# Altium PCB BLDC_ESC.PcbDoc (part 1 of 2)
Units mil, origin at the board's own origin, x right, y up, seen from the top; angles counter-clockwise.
Board outline 1574.8 x 2362.2 mil, 2 copper layers (Top Layer, Bottom Layer), stack 65.792 mil thick; 131 components, 100 nets, 479 pads, 292 vias.
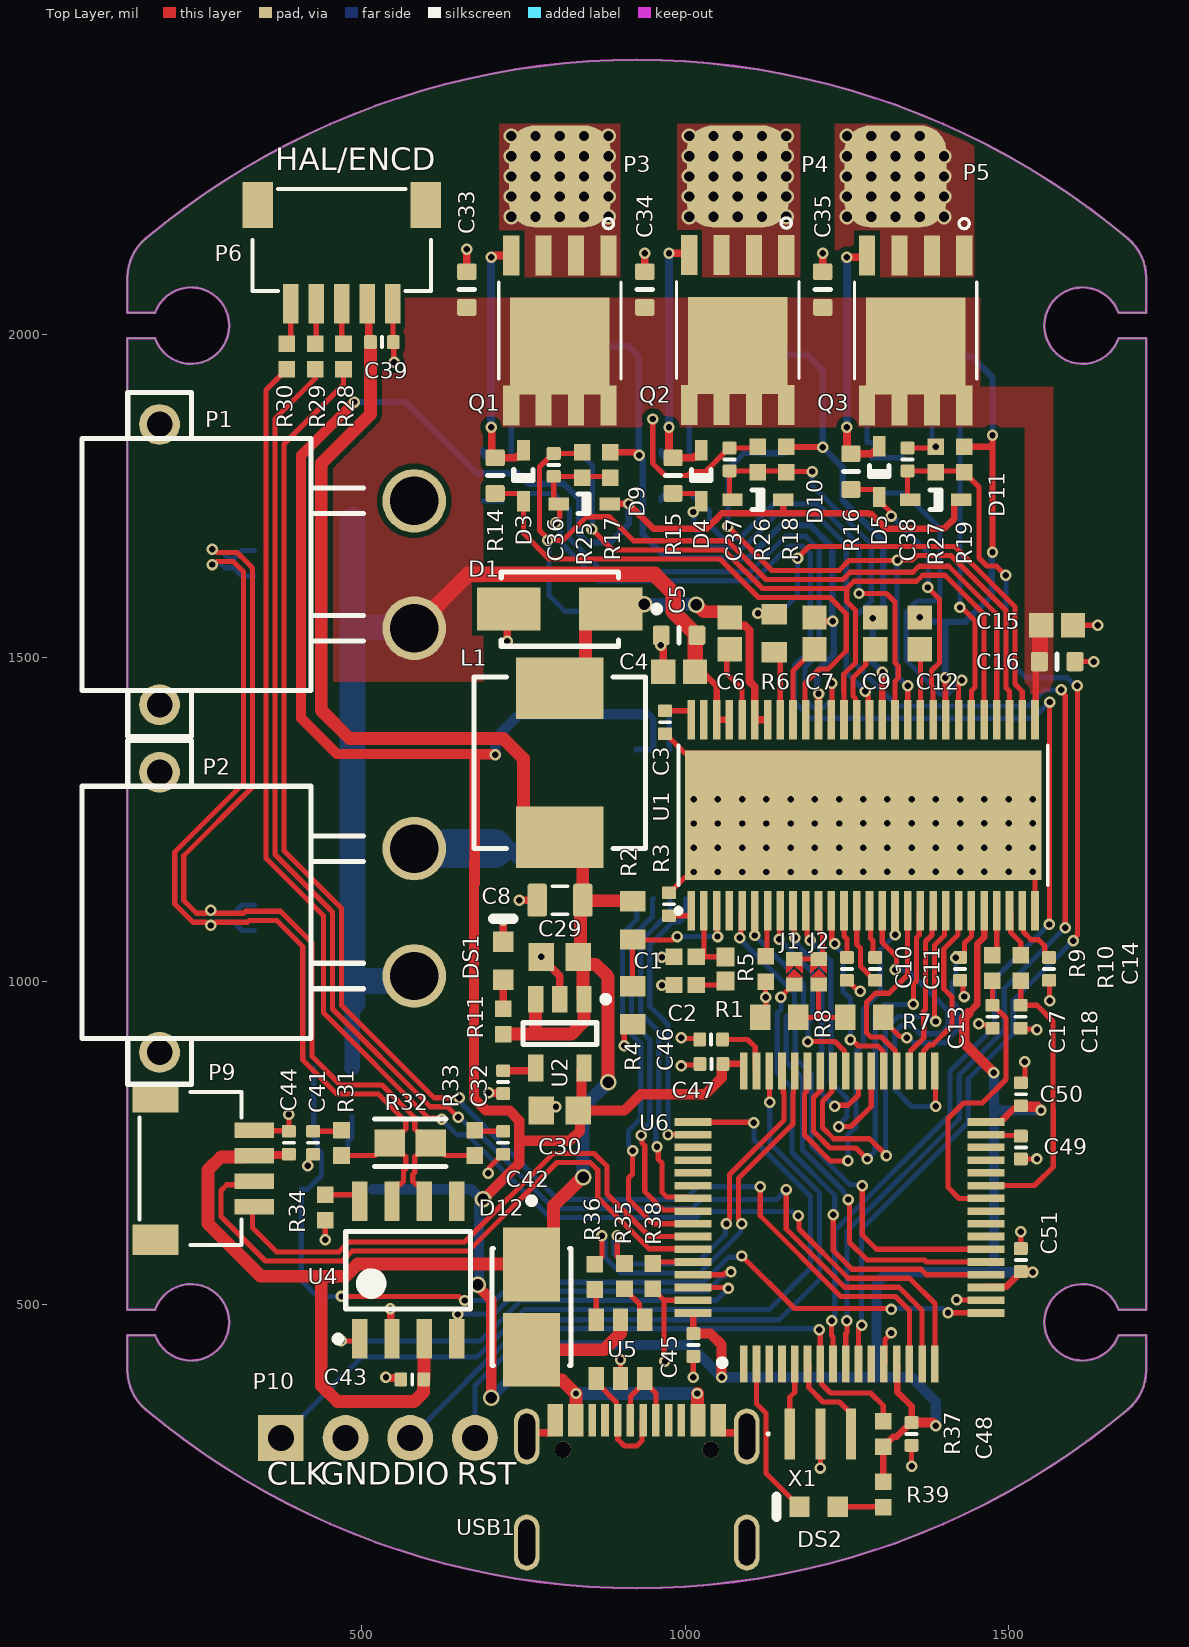
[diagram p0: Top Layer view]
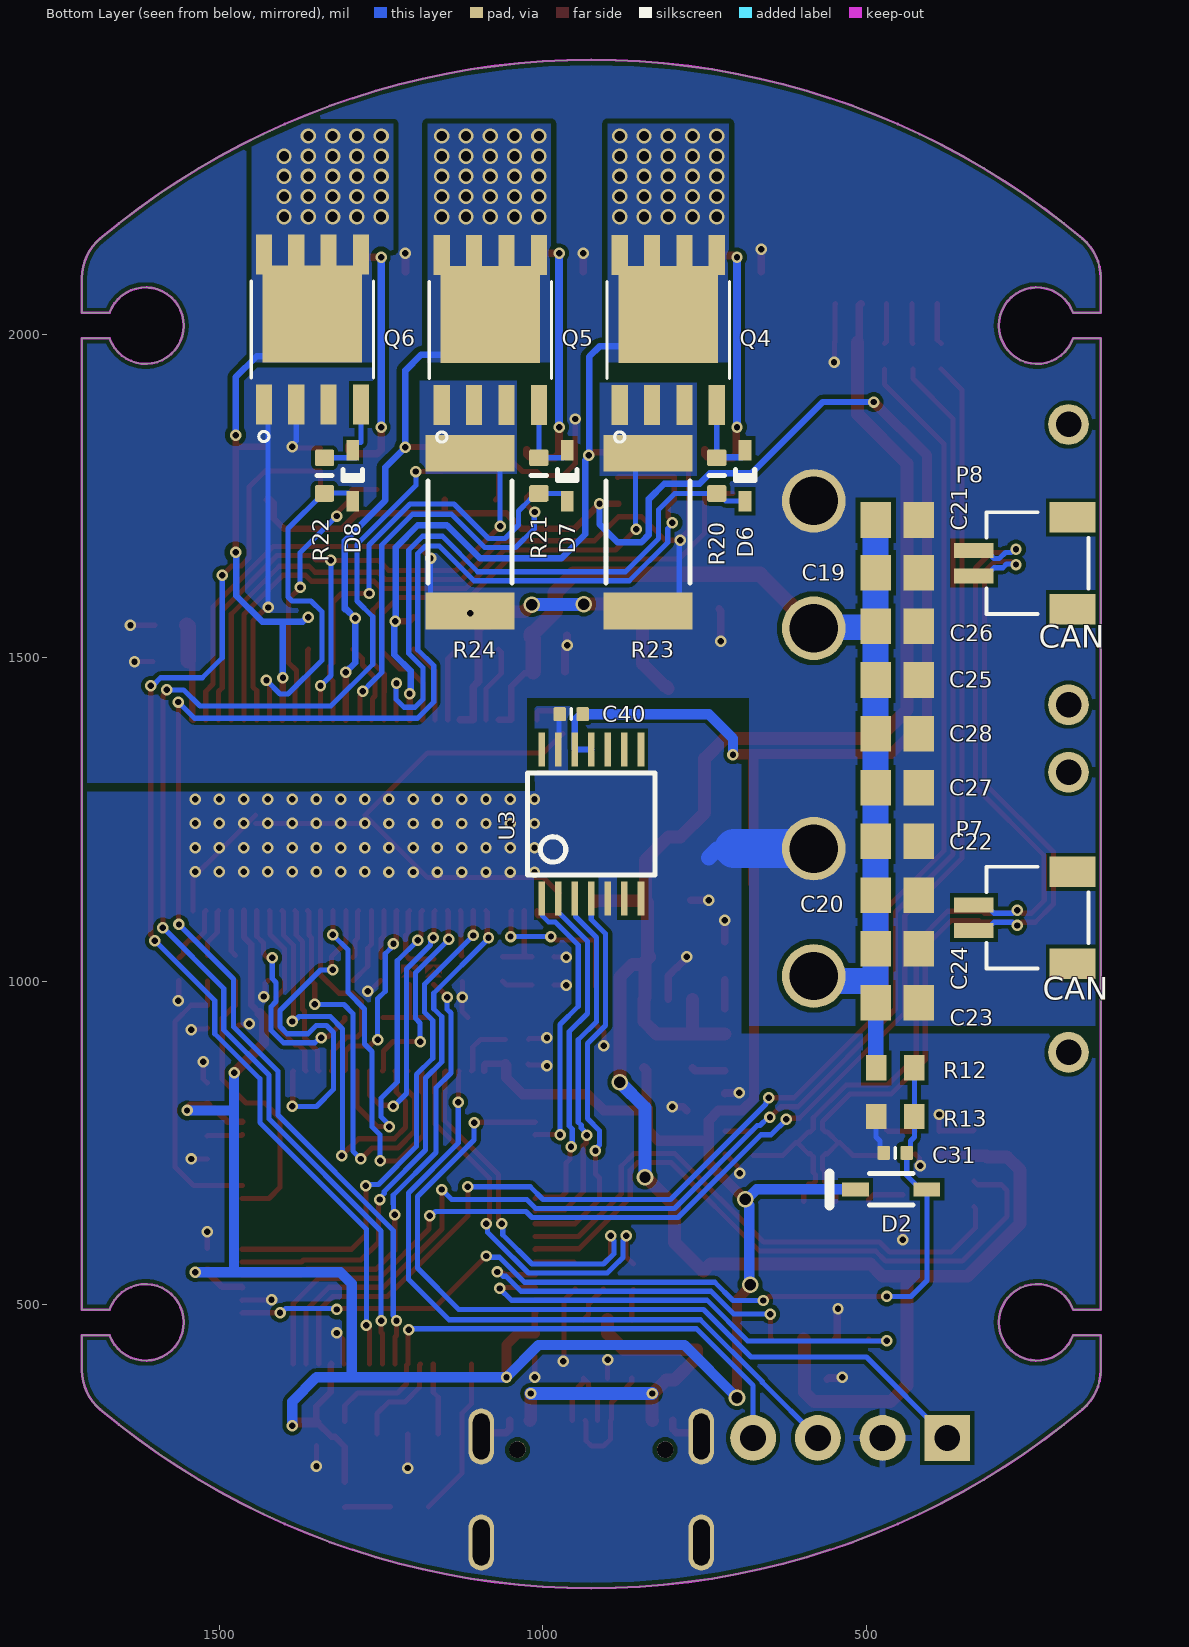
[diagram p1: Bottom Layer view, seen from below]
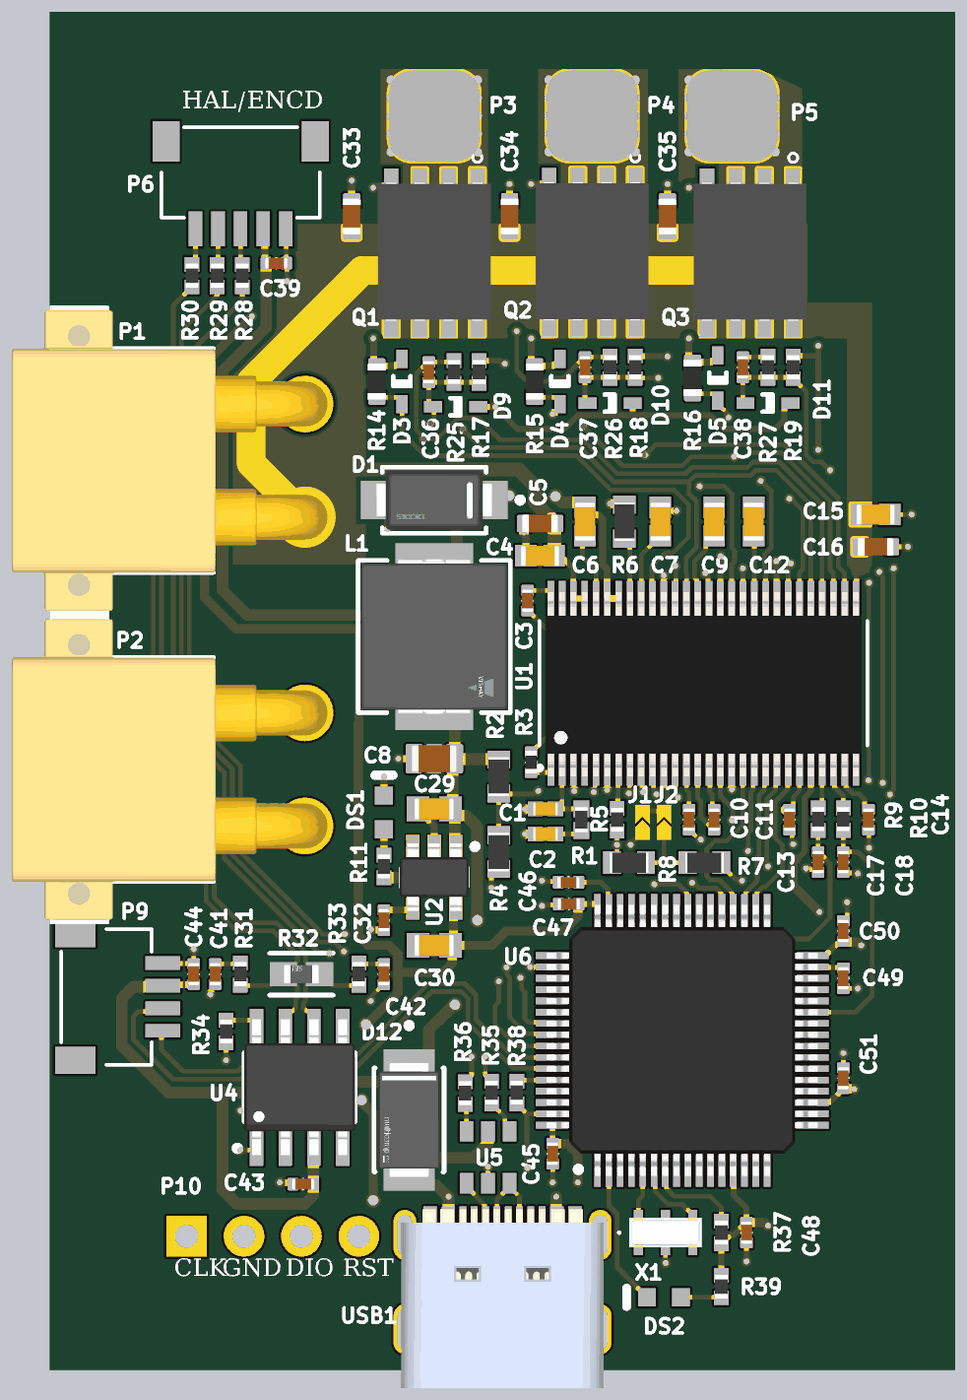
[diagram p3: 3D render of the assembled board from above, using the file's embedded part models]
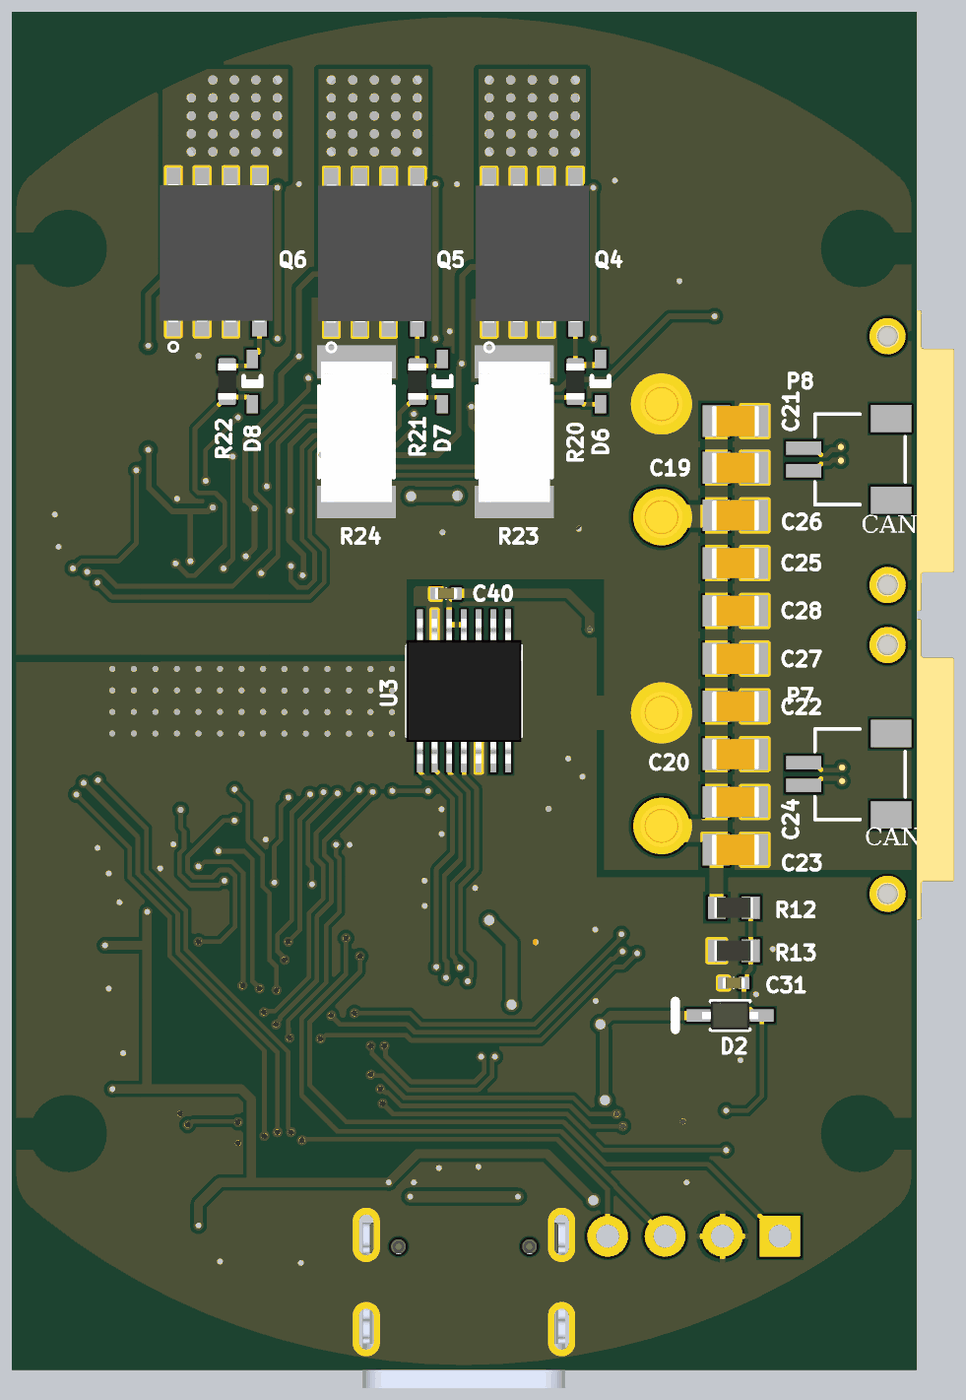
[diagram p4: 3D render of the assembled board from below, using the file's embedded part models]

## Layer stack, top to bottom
Top Solder: solder mask 0.4, Solder Resist, Dk 3.5
Top Layer: signal copper 1.4
Dielectric 1: dielectric 62.9921, FR-4, Dk 4.8
Bottom Layer: signal copper 1.4
Bottom Solder: solder mask 0.4, Solder Resist, Dk 3.5

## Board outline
165.92,338.03 cw(c216.54,398.35) 137.8,398.35 137.8,452.76 180.54,452.76 ccw(c236.22,472.44) 180.54,492.13 137.8,492.13 137.8,1993.35 180.54,1993.35 ccw(c236.22,2013.04) 180.54,2032.72 137.8,2032.72 137.8,2087.13 cw(c216.54,2087.13) 165.92,2147.45 cw(c925.2,1242.74) 1684.48,2147.45 cw(c1633.86,2087.13) 1712.6,2087.13 1712.6,2032.72 1669.85,2032.72 ccw(c1614.17,2013.04) 1669.85,1993.35 1712.6,1993.35 1712.6,492.13 1669.85,492.13 ccw(c1614.17,472.44) 1669.85,452.76 1712.6,452.76 1712.6,398.35 cw(c1633.86,398.35) 1684.48,338.03 cw(c925.2,1242.74)

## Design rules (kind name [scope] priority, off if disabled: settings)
Clearance Clearance_POWER [InNetClass('POWER_OUT')     or InNet('PVDD')] p1: gap=8 ignorepadtopadclearanceinfootprint=TRUE
Clearance [All] p2: gap=6 ignorepadtopadclearanceinfootprint=TRUE except(0: Arc-Region Track-Region SMDPad-Region THPad-Region Via-Region Fill-Region Poly-Region Region-Region)
ComponentClearance [All] p1: gap=0 collisioncheckmode=3 verticalgap=0 showdistances=FALSE
DiffPairsRouting [All] p1: maxlimit=10 minlimit=6 mostfreqgap=6 toplayer_minwidth=8 toplayer_maxwidth=8 toplayer_prefwidth=8 bottomlayer_minwidth=8 bottomlayer_maxwidth=8 bottomlayer_prefwidth=8 maxuncoupledlength=500
MinimumSolderMaskSliver [All] p1: minsoldermaskwidth=0
PolygonConnect PolygonConnect_15 [All vs IsNamedPolygon('PVDD')] p1: connectstyle=Direct reliefconductorwidth=10 reliefentries=4 polygonreliefangle="90 Angle" airgapwidth=10
PolygonConnect PolygonConnect_14 [All vs IsNamedPolygon('GNDA')] p2: connectstyle=Direct reliefconductorwidth=10 reliefentries=4 polygonreliefangle="90 Angle" airgapwidth=10
PolygonConnect PolygonConnect_13 [All vs IsNamedPolygon('GNDA')] p3: thpad.connectstyle=Relief thpad.reliefconductorwidth=10 thpad.reliefentries=4 thpad.polygonreliefangle="90 Angle" thpad.airgapwidth=10 smdpad.connectstyle=Direct smdpad.reliefconductorwidth=10 smdpad.reliefentries=4 smdpad.polygonreliefangle="90 Angle" smdpad.airgapwidth=10 via.connectstyle=Direct via.reliefconductorwidth=10 via.reliefentries=4 via.polygonreliefangle="90 Angle" via.airgapwidth=10
PolygonConnect PolygonConnect_12 [All vs IsNamedPolygon('SL_B')] p4: thpad.connectstyle=Relief thpad.reliefconductorwidth=10 thpad.reliefentries=4 thpad.polygonreliefangle="90 Angle" thpad.airgapwidth=10 smdpad.connectstyle=Direct smdpad.reliefconductorwidth=10 smdpad.reliefentries=4 smdpad.polygonreliefangle="90 Angle" smdpad.airgapwidth=10 via.connectstyle=Direct via.reliefconductorwidth=10 via.reliefentries=4 via.polygonreliefangle="90 Angle" via.airgapwidth=10
PolygonConnect PolygonConnect_11 [All vs IsNamedPolygon('SL_A')] p5: thpad.connectstyle=Relief thpad.reliefconductorwidth=10 thpad.reliefentries=4 thpad.polygonreliefangle="90 Angle" thpad.airgapwidth=10 smdpad.connectstyle=Direct smdpad.reliefconductorwidth=10 smdpad.reliefentries=4 smdpad.polygonreliefangle="90 Angle" smdpad.airgapwidth=10 via.connectstyle=Direct via.reliefconductorwidth=10 via.reliefentries=4 via.polygonreliefangle="90 Angle" via.airgapwidth=10
PolygonConnect PolygonConnect_10 [All vs IsNamedPolygon('SH_C')] p6: thpad.connectstyle=Relief thpad.reliefconductorwidth=10 thpad.reliefentries=4 thpad.polygonreliefangle="90 Angle" thpad.airgapwidth=10 smdpad.connectstyle=Direct smdpad.reliefconductorwidth=10 smdpad.reliefentries=4 smdpad.polygonreliefangle="90 Angle" smdpad.airgapwidth=10 via.connectstyle=Direct via.reliefconductorwidth=10 via.reliefentries=4 via.polygonreliefangle="90 Angle" via.airgapwidth=10
PolygonConnect PolygonConnect_9 [All vs IsNamedPolygon('SH_B')] p7: thpad.connectstyle=Relief thpad.reliefconductorwidth=10 thpad.reliefentries=4 thpad.polygonreliefangle="90 Angle" thpad.airgapwidth=10 smdpad.connectstyle=Direct smdpad.reliefconductorwidth=10 smdpad.reliefentries=4 smdpad.polygonreliefangle="90 Angle" smdpad.airgapwidth=10 via.connectstyle=Direct via.reliefconductorwidth=10 via.reliefentries=4 via.polygonreliefangle="90 Angle" via.airgapwidth=10
PolygonConnect PolygonConnect_8 [All vs IsNamedPolygon('SH_A')] p8: thpad.connectstyle=Relief thpad.reliefconductorwidth=10 thpad.reliefentries=4 thpad.polygonreliefangle="90 Angle" thpad.airgapwidth=10 smdpad.connectstyle=Direct smdpad.reliefconductorwidth=10 smdpad.reliefentries=4 smdpad.polygonreliefangle="90 Angle" smdpad.airgapwidth=10 via.connectstyle=Direct via.reliefconductorwidth=10 via.reliefentries=4 via.polygonreliefangle="90 Angle" via.airgapwidth=10
PolygonConnect PolygonConnect_7 [All vs IsNamedPolygon('SH_C')] p9: thpad.connectstyle=Relief thpad.reliefconductorwidth=10 thpad.reliefentries=4 thpad.polygonreliefangle="90 Angle" thpad.airgapwidth=10 smdpad.connectstyle=Direct smdpad.reliefconductorwidth=10 smdpad.reliefentries=4 smdpad.polygonreliefangle="90 Angle" smdpad.airgapwidth=10 via.connectstyle=Direct via.reliefconductorwidth=10 via.reliefentries=4 via.polygonreliefangle="90 Angle" via.airgapwidth=10
PolygonConnect PolygonConnect_6 [All vs IsNamedPolygon('SH_B')] p10: thpad.connectstyle=Relief thpad.reliefconductorwidth=10 thpad.reliefentries=4 thpad.polygonreliefangle="90 Angle" thpad.airgapwidth=10 smdpad.connectstyle=Direct smdpad.reliefconductorwidth=10 smdpad.reliefentries=4 smdpad.polygonreliefangle="90 Angle" smdpad.airgapwidth=10 via.connectstyle=Direct via.reliefconductorwidth=10 via.reliefentries=4 via.polygonreliefangle="90 Angle" via.airgapwidth=10
PolygonConnect PolygonConnect_5 [All vs IsNamedPolygon('SH_A')] p11: thpad.connectstyle=Relief thpad.reliefconductorwidth=10 thpad.reliefentries=4 thpad.polygonreliefangle="90 Angle" thpad.airgapwidth=10 smdpad.connectstyle=Direct smdpad.reliefconductorwidth=10 smdpad.reliefentries=4 smdpad.polygonreliefangle="90 Angle" smdpad.airgapwidth=10 via.connectstyle=Direct via.reliefconductorwidth=10 via.reliefentries=4 via.polygonreliefangle="90 Angle" via.airgapwidth=10
PolygonConnect PolygonConnect_4 [All vs IsNamedPolygon('SL_B')] p12: thpad.connectstyle=Relief thpad.reliefconductorwidth=10 thpad.reliefentries=4 thpad.polygonreliefangle="90 Angle" thpad.airgapwidth=10 smdpad.connectstyle=Direct smdpad.reliefconductorwidth=10 smdpad.reliefentries=4 smdpad.polygonreliefangle="90 Angle" smdpad.airgapwidth=10 via.connectstyle=Relief via.reliefconductorwidth=10 via.reliefentries=4 via.polygonreliefangle="90 Angle" via.airgapwidth=10
PolygonConnect PolygonConnect_3 [All vs IsNamedPolygon('SL_A')] p13: thpad.connectstyle=Relief thpad.reliefconductorwidth=10 thpad.reliefentries=4 thpad.polygonreliefangle="90 Angle" thpad.airgapwidth=10 smdpad.connectstyle=Direct smdpad.reliefconductorwidth=10 smdpad.reliefentries=4 smdpad.polygonreliefangle="90 Angle" smdpad.airgapwidth=10 via.connectstyle=Relief via.reliefconductorwidth=10 via.reliefentries=4 via.polygonreliefangle="90 Angle" via.airgapwidth=10
PolygonConnect PolygonConnect_2 [All vs IsNamedPolygon('GND')] p14: thpad.connectstyle=Relief thpad.reliefconductorwidth=10 thpad.reliefentries=4 thpad.polygonreliefangle="90 Angle" thpad.airgapwidth=10 smdpad.connectstyle=Direct smdpad.reliefconductorwidth=10 smdpad.reliefentries=4 smdpad.polygonreliefangle="90 Angle" smdpad.airgapwidth=10 via.connectstyle=Direct via.reliefconductorwidth=10 via.reliefentries=4 via.polygonreliefangle="90 Angle" via.airgapwidth=10
PolygonConnect PolygonConnect_1 [All vs IsNamedPolygon('PVDD')] p15: thpad.connectstyle=Relief thpad.reliefconductorwidth=10 thpad.reliefentries=4 thpad.polygonreliefangle="90 Angle" thpad.airgapwidth=10 smdpad.connectstyle=Direct smdpad.reliefconductorwidth=10 smdpad.reliefentries=4 smdpad.polygonreliefangle="90 Angle" smdpad.airgapwidth=10 via.connectstyle=Direct via.reliefconductorwidth=10 via.reliefentries=4 via.polygonreliefangle="90 Angle" via.airgapwidth=10
PolygonConnect [All] p16: connectstyle=Relief reliefconductorwidth=10 reliefentries=4 polygonreliefangle="90 Angle" airgapwidth=10
RoutingVias RoutingVias_signal [All] p1: holewidth=9.84 width=17.72 viastyle="Through Hole" minholewidth=9.84 minwidth=17.72 maxholewidth=17.72 maxwidth=25.59
SilkToSilkClearance [All] p1: silktosilkclearance=0
SilkToSolderMaskClearance [IsPad] p1: minsilkscreentomaskgap=0 clearancetoexposedcopper=TRUE
SolderMaskExpansion [All] p1: expansion=4 istentingtop=FALSE
UnRoutedNet [All] p1: checkbadconnections=TRUE
Width HIGH_POWER [InNet('PVDD')or InNetClass('POWER_OUT')  or InNet('GND')] p1: maxlimit=60 minlimit=8 preferedwidth=24
Width MID_POWER [InNetClass('MID_POWER')  or InNet('VBUS')] p2: maxlimit=20 minlimit=12 preferedwidth=20
Width LOW_POWER [InNet('+3V3')] p3: maxlimit=16 minlimit=10 preferedwidth=10
Width signal [All] p4: maxlimit=12 minlimit=8 preferedwidth=8
24 further rules are at their usual default settings.

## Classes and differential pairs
net class POWER_OUT: SH_A SH_B SH_C
net class MID_POWER: +5V NetC6_2
component class "rotor angle sensor": C39 C40 P6 R28 R29 R30 U3
component class "power MOSFET": C19 C20 C21 C22 C23 C24 C25 C26 C27 C28 C29 C30 C31 C32 C33 C34 C35 C36 C37 C38 D2 D3 D4 D5 D6 D7 D8 D9 D10 D11 DS1 P1 P2 P3 P4 P5 Q1 Q2 Q3 Q4 Q5 Q6 R11 R12 R13 R14 R15 R16 R17 R18 R19 R20 R21 R22 R23 R24 R25 R26 R27 U2
component class "main controller": C44 C45 C46 C47 C48 C49 C50 C51 D12 DS2 P9 P10 R35 R36 R37 R38 R39 U5 U6 USB1 X1
component class "gate driver": C1 C2 C3 C4 C5 C6 C7 C8 C9 C10 C11 C12 C13 C14 C15 C16 C17 C18 D1 J1 J2 R1 R2 R3 R4 R5 R6 R7 R8 R9 R10 U1
component class CAN: C41 C42 C43 P7 P8 R31 R32 R33 R34 U4
differential pair CAN1: +CAN1_P -CAN1_N
differential pair USB: +USB_P -USB_N

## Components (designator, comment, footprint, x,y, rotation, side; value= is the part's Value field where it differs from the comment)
C1 "Capacitor 6.8 nF +/- 10% 16 V 0402" CAPC1005X56X25NL10T15 1000,1037.5 r0 top value=120pF
C2 "Capacitor 6.8 nF +/- 10% 16 V 0402" CAPC1005X56X25NL10T15 1000,993.75 r0 top value=6.8nF
C3 "Capacitor 22nF +/-20% 10V 0402" CAPC0402(1005)60_L 968.75,1400 r270 top value=15nF
C4 "Capacitor 100 nF +/-10% 50 V 0603" CAPC1608X90X40NL10T20 990.6,1478.1 r180 top value=100nF
C5 "Capacitor 4.7µF +/-20% 10V 0603" CAPC0603(1608)100_L 990.6,1534.35 r180 top value=4.7µF
C6 "Capacitor 100 nF +/-10% 50 V 0603" CAPC1608X90X40NL10T20 1068.75,1537.5 r90 top value=100nF
C7 "Capacitor 100 nF +/-10% 50 V 0603" CAPC1608X90X40NL10T20 1200,1537.5 r90 top value=100nF
C8 "Capacitor 47µF +/-40% 6.3V 0805" CAPC0805(2012)145_L 806.25,1125 r180 top value=47µF
C9 "Capacitor 100 nF +/-10% 50 V 0603" CAPC1608X90X40NL10T20 1293.75,1537.5 r90 top value=100nF
C10 "Capacitor 2,2µF +/-20% 10V 0402" CAPC0402(1005)60_L 1250,1018.75 r270 top value=2.2µF
C11 "Capacitor 22nF +/-20% 10V 0402" CAPC0402(1005)60_L 1293.75,1018.75 r90 top value=22nF
C12 "Capacitor 100 nF +/-10% 50 V 0603" CAPC1608X90X40NL10T20 1362.5,1537.5 r90 top value=100nF
C13 "Capacitor 1µF +/-20% 10V 0402" CAPC0402(1005)60_L 1425,1018.75 r270 top value=1µF
C14 "Capacitor 1µF +/-20% 10V 0402" CAPC0402(1005)60_L 1562.5,1018.75 r270 top value=1µF
C15 "Capacitor 100 nF +/-10% 50 V 0603" CAPC1608X90X40NL10T20 1575,1550 r0 top value=100nF
C16 "Capacitor 4.7µF +/-20% 10V 0603" CAPC0603(1608)100_L 1575,1493.75 r0 top value=4.7µF
C17 "Capacitor 22nF +/-20% 10V 0402" CAPC0402(1005)60_L 1474.9,944.9 r270 top value=2.2nF
C18 "Capacitor 22nF +/-20% 10V 0402" CAPC0402(1005)60_L 1518.65,944.9 r270 top value=2.2nF
C19 "Capacitor 10 uF +/- 10% 16 V 0805" CAPC2013X135X45NL10T25 452.21,1631.25 r0 bottom value=10µF
C20 "Capacitor 10 uF +/- 10% 16 V 0805" CAPC2013X135X45NL10T25 452.38,1132.8 r0 bottom value=10µF
C21 "Capacitor 10 uF +/- 10% 16 V 0805" CAPC2013X135X45NL10T25 452.21,1712.5 r0 bottom value=10µF
C22 "Capacitor 10 uF +/- 10% 16 V 0805" CAPC2013X135X45NL10T25 452.38,1215.91 r0 bottom value=10µF
C23 "Capacitor 10 uF +/- 10% 16 V 0805" CAPC2013X135X45NL10T25 452.38,966.56 r0 bottom value=10µF
C24 "Capacitor 10 uF +/- 10% 16 V 0805" CAPC2013X135X45NL10T25 452.38,1049.68 r0 bottom value=10µF
C25 "Capacitor 10 uF +/- 10% 16 V 0805" CAPC2013X135X45NL10T25 452.38,1465.27 r0 bottom value=10µF
C26 "Capacitor 10 uF +/- 10% 16 V 0805" CAPC2013X135X45NL10T25 452.38,1548.38 r0 bottom value=10µF
C27 "Capacitor 10 uF +/- 10% 16 V 0805" CAPC2013X135X45NL10T25 452.38,1299.03 r0 bottom value=10µF
C28 "Capacitor 10 uF +/- 10% 16 V 0805" CAPC2013X135X45NL10T25 452.38,1382.15 r0 bottom value=10µF
C29 "Capacitor 1uF +/- 10% 16V 0603" CAPC1608X90X35ML15T15 806.25,1037.5 r0 top value=1µF
C30 "Capacitor 1uF +/- 10% 16V 0603" CAPC1608X90X35ML15T15 806.25,800 r0 top value=2.2µF
C31 "Capacitor 100nF +/-20% 50V 0402" CAPC0402(1005)60_L 455.36,734.4 r180 bottom value=100nF
C32 "Capacitor 10nF +/-20% 50V 0402" CAPC0402(1005)60_L 718.75,843.75 r90 top value=10nF
C33 "Capacitor 4.7µF +/-20% 10V 0603" CAPC0603(1608)100_L 662.5,2068.75 r90 top value=2.2µF
C34 "Capacitor 4.7µF +/-20% 10V 0603" CAPC0603(1608)100_L 937.5,2068.75 r90 top value=2.2µF
C35 "Capacitor 4.7µF +/-20% 10V 0603" CAPC0603(1608)100_L 1212.5,2068.75 r90 top value=2.2µF
C36 "Capacitor 100nF +/-20% 50V 0402" CAPC0402(1005)60_L 796.85,1797.79 r270 top value=100nF
C37 "Capacitor 100nF +/-20% 50V 0402" CAPC0402(1005)60_L 1068.75,1806.25 r270 top value=100nF
C38 "Capacitor 100nF +/-20% 50V 0402" CAPC0402(1005)60_L 1343.75,1806.25 r270 top value=100nF
C39 "Capacitor 100nF +/-20% 50V 0402" CAPC0402(1005)60_L 531.25,1987.5 r180 top value=100nF(0402)
C40 "Capacitor 100nF +/-20% 50V 0402" CAPC0402(1005)60_L 956.25,1412.5 r180 bottom value=100nF(0402)
C41 "Capacitor 100nF +/-20% 50V 0402" CAPC0402(1005)60_L 425,750 r90 top value=560pF(0402)
C42 "Capacitor 100nF +/-20% 50V 0402" CAPC0402(1005)60_L 718.75,750 r90 top value=560pF(0402)
C43 "Capacitor 100nF +/-20% 50V 0402" CAPC0402(1005)60_L 578.1,384.35 r0 top value=100nF(0402)
C44 "Capacitor 100nF +/-20% 50V 0402" CAPC0402(1005)60_L 387.5,750 r270 top value=100nF(0402)
C45 "Capacitor 100nF +/-20% 50V 0402" CAPC0402(1005)60_L 1012.5,437.5 r90 top value=100nF(0402)
C46 "Capacitor 100nF +/-20% 50V 0402" CAPC0402(1005)60_L 1040.08,909.82 r0 top value=100nF(0402)
C47 "Capacitor 100nF +/-20% 50V 0402" CAPC0402(1005)60_L 1040.6,871.85 r0 top value=100nF(0402)
C48 "Capacitor 100nF +/-20% 50V 0402" CAPC0402(1005)60_L 1350,300 r90 top value=100nF(0402)
C49 "Capacitor 100nF +/-20% 50V 0402" CAPC0402(1005)60_L 1518.75,742.72 r90 top value=100nF(0402)
C50 "Capacitor 100nF +/-20% 50V 0402" CAPC0402(1005)60_L 1518.75,825 r270 top value=100nF(0402)
C51 "Capacitor 100nF +/-20% 50V 0402" CAPC0402(1005)60_L 1518.75,568.75 r270 top value=100nF(0402)
D1 "B330A-13-F" FP-SMA-MFG 806.25,1575 r180 top value=200pF
D2 "1N4148WS" FAIR-SOD-323_V 461.61,678.15 r0 bottom
D3 "1N4148WT" FAIR-SOD-523F-2_V 750,1781.25 r90 top
D4 "1N4148WT" FAIR-SOD-523F-2_V 1025,1781.25 r90 top
D5 "1N4148WT" FAIR-SOD-523F-2_V 1300,1787.5 r90 top
D6 "1N4148WT" FAIR-SOD-523F-2_V 687.5,1781.25 r90 bottom
D7 "1N4148WT" FAIR-SOD-523F-2_V 962.5,1781.25 r90 bottom
D8 "1N4148WT" FAIR-SOD-523F-2_V 1293.75,1781.25 r90 bottom
D9 "1N4148WT" FAIR-SOD-523F-2_V 843.75,1737.5 r180 top
D10 "1N4148WT" FAIR-SOD-523F-2_V 1112.5,1743.75 r180 top
D11 "1N4148WT" FAIR-SOD-523F-2_V 1387.5,1743.75 r180 top
D12 "1N4007 SMD" FP-1N4007_SMD-IPC_A 762.5,496.06 r270 top
DS1 "HSMH-C190" AVAG-HSMX-C190_V 718.75,1031.25 r90 top
DS2 "LTST-C190KSKT" LTST-C190KSKT_V 1206.25,187.5 r180 top
J1 "JUMPER" JUMPER 1168.75,1012.5 r0 top
J2 "JUMPER" JUMPER 1206.25,1012.5 r0 top
L1 "22uH" FP-IHLP-2525CZ-FP_2_413x3-MFG 806.25,1337.5 r270 top
P1 "XT30PW-M" XT30PW-M 581.25,1643.75 r90 top
P2 "XT30PW-M" XT30PW-M 581.25,1106.25 r90 top
P3 "DP-01" DP-01 806.25,2243.75 r0 top
P4 "DP-01" DP-01 1081.25,2243.75 r0 top
P5 "DP-01" DP-01 1325,2243.75 r0 top
P6 "JST_SH-05P" SH-5P-SIDE 528.15,2046.9 r180 top
P7 "JST_SH-02P" SH-2P-SIDE 333.81,1097.88 r90 bottom
P8 "JST_SH-02P" SH-2P-SIDE 333.81,1645.87 r90 bottom
P9 "JST_SH-04P" SH-04-SIDE 333.81,749.61 r270 top
P10 "HEADER-4P" female_header-4p 375,293.75 r0 top
Q1 "MDU1512RH" PDFN56 806.25,2005.46 r180 top
Q2 "MDU1512RH" PDFN56 1081.25,2006.25 r180 top
Q3 "MDU1512RH" PDFN56 1356.25,2005.46 r180 top
Q4 "MDU1512RH" PDFN56 806.25,2006.25 r180 bottom
Q5 "MDU1512RH" PDFN56 1081.25,2006.25 r180 bottom
Q6 "MDU1512RH" PDFN56 1356.25,2007.04 r180 bottom
R1 "Resistor 15k +/-1% 0402 63 mW" RESC1005X40X25ML10T10 1062.5,1018.75 r90 top value=15k
R2 "Resistor 10k +/-1% 0603 100 mW" RESC1608X55X25ML10T15 918.75,1093.75 r90 top value=18k
R3 "Resistor 200K +/-1 % 0402 63 mW" RESC0402(1005)_L 975,1118.75 r270 top value=200k
R4 "Resistor 10k +/-1% 0603 100 mW" RESC1608X55X25ML10T15 918.75,962.5 r90 top value=3k3
R5 "Resistor 10k +/-1% 0402 100 mW" RESC1005X40X25ML05T05 1124.85,1018.9 r270 top value=10k
R6 "Resistor 10k +/-1% 0603 100 mW" RESC1608X55X25ML10T15 1137.5,1537.5 r90 top value=1M
R7 "Resistor 10k +/-1% 0603 100 mW" RESC1608X55X25ML10T15 1276.72,943.75 r0 top value=RA
R8 "Resistor 10k +/-1% 0603 100 mW" RESC1608X55X25ML10T15 1145.47,943.75 r0 top value=RB
R9 "Resistor 10k +/-1% 0402 100 mW" RESC1005X40X25ML05T05 1474.9,1019.9 r270 top value=56R
R10 "Resistor 10k +/-1% 0402 100 mW" RESC1005X40X25ML05T05 1518.65,1019.9 r270 top value=56R
R11 "Resistor 0R +/- 5% 0402 100 mW" RESC1005X40X25ML05T05 718.75,937.5 r90 top value=1k(0402)
R12 "Resistor 10k +/-1% 0603 100 mW" RESC1608X55X25ML10T15 455.36,865.65 r180 bottom value=39k
R13 "Resistor 10k +/-1% 0603 100 mW" RESC1608X55X25ML10T15 455.36,790.65 r0 bottom value=2k2
R14 "Resistor 120R +/-5 % 0603 0.1 W" RESC0603(1608)_L 706.25,1781.25 r90 top value=10R
R15 "Resistor 120R +/-5 % 0603 0.1 W" RESC0603(1608)_L 981.25,1781.25 r90 top value=10R
R16 "Resistor 120R +/-5 % 0603 0.1 W" RESC0603(1608)_L 1256.25,1787.5 r90 top value=10R
R17 "Resistor 0R +/- 5% 0402 100 mW" RESC1005X40X25ML05T05 884.35,1797.79 r90 top value=39k(0402)
R18 "Resistor 0R +/- 5% 0402 100 mW" RESC1005X40X25ML05T05 1156.25,1806.25 r90 top value=39k(0402)
R19 "Resistor 0R +/- 5% 0402 100 mW" RESC1005X40X25ML05T05 1431.25,1806.25 r90 top value=39k(0402)
R20 "Resistor 120R +/-5 % 0603 0.1 W" RESC0603(1608)_L 731.25,1781.25 r90 bottom value=10R
R21 "Resistor 120R +/-5 % 0603 0.1 W" RESC0603(1608)_L 1006.25,1781.25 r90 bottom value=10R
R22 "Resistor 120R +/-5 % 0603 0.1 W" RESC0603(1608)_L 1337.5,1781.25 r90 bottom value=10R
R23 "0.001R-2512" FP-CRCW2512-e3-MFG 837.5,1693.75 r270 bottom
R24 "0.001R-2512" FP-CRCW2512-e3-MFG 1112.5,1693.75 r270 bottom
R25 "Resistor 0R +/- 5% 0402 100 mW" RESC1005X40X25ML05T05 840.6,1797.79 r270 top value=2k2(0402)
R26 "Resistor 0R +/- 5% 0402 100 mW" RESC1005X40X25ML05T05 1112.5,1806.25 r270 top value=2k2(0402)
R27 "Resistor 0R +/- 5% 0402 100 mW" RESC1005X40X25ML05T05 1387.5,1806.25 r270 top value=2k2(0402)
R28 "Resistor 0R +/- 5% 0402 100 mW" RESC1005X40X25ML05T05 471.9,1965.65 r270 top value=0R(0402)
R29 "Resistor 0R +/- 5% 0402 100 mW" RESC1005X40X25ML05T05 428.15,1965.65 r270 top value=0R(0402)
R30 "Resistor 0R +/- 5% 0402 100 mW" RESC1005X40X25ML05T05 384.4,1965.65 r270 top value=0R(0402)
R31 "Resistor 0R +/- 5% 0402 100 mW" RESC1005X40X25ML05T05 468.75,750 r90 top value=100R(0402)
R32 "120R(0603)" FP-RMCF0603-IPC_A 575,750 r180 top
R33 "Resistor 0R +/- 5% 0402 100 mW" RESC1005X40X25ML05T05 675,750 r90 top value=100R(0402)
R34 "Resistor 0R +/- 5% 0402 100 mW" RESC1005X40X25ML05T05 443.75,650 r90 top value=4k7(0402)
R35 "Resistor 0R +/- 5% 0402 100 mW" RESC1005X40X25ML05T05 906.25,543.75 r270 top value=100R(0402)
R36 "Resistor 0R +/- 5% 0402 100 mW" RESC1005X40X25ML05T05 860.14,542.91 r270 top value=100R(0402)
R37 "Resistor 0R +/- 5% 0402 100 mW" RESC1005X40X25ML05T05 1306.25,300 r90 top value=10k(0402)
R38 "Resistor 0R +/- 5% 0402 100 mW" RESC1005X40X25ML05T05 950,543.75 r270 top value=10k(0402)
R39 "Resistor 0R +/- 5% 0402 100 mW" RESC1005X40X25ML05T05 1306.25,206.25 r270 top value=1k(0402)
U1 "DRV8302" HTSSOP-56 1009.25,1108.61 r0 top
U2 "LP2985-33DBVR" TI-DBV5_V 806.25,918.75 r270 top
U3 "AS5047P" TSSOP-14 925.2,1242.76 r180 bottom
U4 "MCP2551-I/SN" MCHP-SN8_V 571.85,553.1 r90 top
U5 "USBLC6-2SC6Y" SOT23-6 900,431.25 r0 top
U6 "STM32F405RGT6" QFP50P1200X1200X160-64N 1238.28,634.57 r90 top
USB1 "USB-C" USB-C-A40-00119 925.2,37.5 r0 top
X1 "12MHz" MURA-CSTCE_G_V 1209.01,300 r0 top

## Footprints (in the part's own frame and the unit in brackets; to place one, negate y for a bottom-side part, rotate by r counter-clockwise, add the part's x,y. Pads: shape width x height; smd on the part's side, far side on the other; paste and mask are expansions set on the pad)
AVAG-HSMX-C190_V [mm] "SMD, 2-Leads, Body 1.6x0.8mm, Height 0.9mm"
  rect 0.8x0.8 smd: 1(-0.75,0) 2(0.75,0)
  silkscreen extent 1.65,-0.4 1.65,0.4, body extent -0.8,-0.4 0.8,0.4, height 0.9
CAPC0402(1005)60_L [mm] "Chip Capacitor, Body 1.0x0.5mm, Height 0.6mm, IPC High Density"
  rrect25% 0.5x0.55 smd: 1(-0.45,0) 2(0.45,0)
  silkscreen extent 0,-0.2 0,0.2, body extent -0.5,-0.25 0.5,0.25, height 0.6
CAPC0603(1608)100_L [mm] "Chip Capacitor, Body 1.6x0.8mm, Height 1.0mm, IPC High Density"
  rrect25% 0.66x0.76 smd: 1(-0.7,0) 2(0.7,0)
  silkscreen extent 0,-0.3 0,0.3, body extent -0.8,-0.4 0.8,0.4, height 0.95
CAPC0805(2012)145_L [mm] "Chip Capacitor, Body 2.0x1.2mm, Height 1.45mm, IPC High Density"
  rrect25% 0.76x1.3 smd: 1(-0.9,0) 2(0.89,0)
  silkscreen extent -0.3,-0.55 0.3,0.55, body extent -1,-0.6 1,0.6, height 1.45
CAPC1005X56X25NL10T15 [mm] "Chip Capacitor, 2-Leads, Body 1.10x0.60mm, IPC Medium Density"
  rect 0.68x0.64 smd: 1(-0.44,0) 2(0.44,0)
  body extent -0.55,-0.3 0.55,0.3, height 0.56
CAPC1608X90X35ML15T15 [mm] "Chip Capacitor, 2-Leads, Body 1.75x0.95mm, IPC Low Density"
  rect 1x1.1 smd: 1(-0.725,0) 2(0.725,0)
  body extent -0.87,-0.48 0.87,0.48, height 0.9
CAPC1608X90X40NL10T20 [mm] "Chip Capacitor, 2-Leads, Body 1.70x0.90mm, IPC Medium Density"
  rect 0.95x0.95 smd: 1(-0.625,0) 2(0.625,0)
  body extent -0.85,-0.45 0.85,0.45, height 0.9
CAPC2013X135X45NL10T25 [mm] "Chip Capacitor, 2-Leads, Body 2.10x1.35mm, IPC Medium Density"
  rect 1.2x1.4 smd: 1(-0.85,0) 2(0.85,0)
  body extent -1.05,-0.67 1.05,0.67, height 1.35
DP-01 [mm]
  rrect50% 4x4 smd: X(0,0)
FAIR-SOD-323_V [mm] "SODFL, 2-Leads, Body 1.25x1.7mm"
  rect 1.05x0.55 smd: 1(-1.4,0) 2(1.4,0)
  silkscreen extent -0.85,-0.63 2.43,0.63, body extent -1.25,-0.63 1.25,0.63, height 1
FAIR-SOD-523F-2_V [mm] "SMD, 2-Leads, Body 1.2x0.8mm, Height 0.7mm"
  rect 0.8x0.5 smd: 1(-1,0) 2(1,0)
  silkscreen extent -0.2,-0.38 0.24,0.38, body extent -0.6,-0.4 0.6,0.4, height 0.71
female_header-4p [mm]
  rect 1.8x1.8 hole 1.02: 1(0,0)
  round 1.8 hole 1.02: 2(2.54,0) 3(5.08,0) 4(7.62,0)
FP-1N4007_SMD-IPC_A [mm]
  rect 2.9x2.25 smd paste+0 mask+0: 1(-1.675,0) 2(1.675,0)
  silkscreen extent -4.3,-1.55 2.3,1.55, body extent -3.6,-1.95 3.6,1.95, height 0.25
FP-CRCW2512-e3-MFG [mm]
  rect 1.45x3.5 smd paste+0 mask+0: 1(-3.1,0) 2(3.1,0)
  silkscreen extent -2,-1.65 2,1.65, body extent -3.15,-1.58 3.15,1.58, height 0.7
FP-IHLP-2525CZ-FP_2_413x3-MFG [mil]
  rect 95x135 smd paste+0 mask+0: 1(-115,0) 2(115,0)
  silkscreen extent -132,-132 132,132, body extent -166,-136 166,136, height 10
FP-RMCF0603-IPC_A [mil]
  rect 47.48x41.66 smd paste+0 mask+0: 1(-31.54,0) 2(31.54,0)
  silkscreen extent -55,-37 55,37, body extent -75,-41 75,41, height 10
FP-SMA-MFG [mm]
  rect 2.5x1.7 smd paste+0 mask+0: 1(-2,0) 2(2,0)
  silkscreen extent -3.93,-1.46 2.3,1.46, body extent -3.35,-1.56 3.35,1.56, height 0.25
HTSSOP-56 [mm]
  rect 0.3x1.55 smd: 1(0,0) 2(0.5,0) 3(1,0) 4(1.5,0) 5(2,0) 6(2.5,0) 7(3,0) 8(3.5,0) 9(4,0) 10(4.5,0) 11(5,0) 12(5.5,0) 13(6,0) 14(6.5,0) 15(7,0) 16(7.5,0) 17(8,0) 18(8.5,0) 19(9,0) 20(9.5,0) 21(10,0) 22(10.5,0) 23(11,0) 24(11.5,0) 25(12,0) 26(12.5,0) 27(13,0) 28(13.5,0) 29(13.5,7.5) 30(13,7.5) 31(12.5,7.5) 32(12,7.5) 33(11.5,7.5) 34(11,7.5) 35(10.5,7.5) 36(10,7.5) 37(9.5,7.5) 38(9,7.5) 39(8.5,7.5) 40(8,7.5) 41(7.5,7.5) 42(7,7.5) 43(6.5,7.5) 44(6,7.5) 45(5.5,7.5) 46(5,7.5) 47(4.5,7.5) 48(4,7.5) 49(3.5,7.5) 50(3,7.5) 51(2.5,7.5) 52(2,7.5) 53(1.5,7.5) 54(1,7.5) 55(0.5,7.5) 56(0,7.5)
  rect 14x5.1 smd mask-2539.97: EXP(6.75,3.75)
  silkscreen extent -0.6,-0.1 14,6.5, body extent -0.29,-0.37 13.79,7.77, height 1.14
JUMPER [mm]
  rect 0.65x0.55 smd paste-2.54 mask-2.54: 1(0,-0.45) 2(0,0.55)
  Top Layer region: -0.325,-0.041 0,0.284 0.325,-0.041 0.325,0.318 -0.325,0.318
  Top Layer region: -0.325,-0.175 0.003,0.152 0.325,-0.175
LTST-C190KSKT_V [mm] "SMD, 2-Leads, Body 1.6x0.8mm"
  rect 0.8x0.8 smd: 1(-0.75,0) 2(0.75,0)
  silkscreen extent 1.65,-0.4 1.65,0.4, body extent -0.8,-0.4 0.8,0.4, height 0.9
MCHP-SN8_V [mm] "SOIC, 8-Leads, Body 4.9x3.9mm, Pitch 1.27mm"
  rect 1.55x0.6 smd: 1(-2.7,1.905) 2(-2.7,0.635) 3(-2.7,-0.635) 4(-2.7,-1.905) 5(2.7,-1.905) 6(2.7,-0.635) 7(2.7,0.635) 8(2.7,1.905)
  silkscreen extent -2.82,-2.45 1.53,2.88, body extent -3,-2.45 3,2.45, height 1.75
MURA-CSTCE_G_V [mm] "SMD, 3-Leads, Body 3.2x1.3mm, Pitch 1.2mm"
  rect 0.4x2 smd: 1(-1.2,0) 2(0,0) 3(1.2,0)
  silkscreen extent -2.1,-0.05 -2,0.05, body extent -1.6,-0.65 1.6,0.65, height 0.7
PDFN56 [mil]
  rect 25x61.81 smd: 1(-75,-115.94) 2(-25,-115.94) 3(25,-115.94) 4(75,-115.94) 5(75,115.94) 6(25,115.94) 7(-25,115.94) 8(-75,115.94)
  rect 153.94x150 smd: EXT(0,24.21)
  silkscreen extent -94,-173 94,75, body extent -98,-122 98,118, height 37
QFP50P1200X1200X160-64N [mil]
  rect 57.09x11.81 smd: 1(-226.38,147.64) 2(-226.38,127.95) 3(-226.38,108.27) 4(-226.38,88.58) 5(-226.38,68.9) 6(-226.38,49.21) 7(-226.38,29.53) 8(-226.38,9.84) 9(-226.38,-9.84) 10(-226.38,-29.53) 11(-226.38,-49.21) 12(-226.38,-68.9) 13(-226.38,-88.58) 14(-226.38,-108.27) 15(-226.38,-127.95) 16(-226.38,-147.64) 33(226.38,-147.64) 34(226.38,-127.95) 35(226.38,-108.27) 36(226.38,-88.58) 37(226.38,-68.9) 38(226.38,-49.21) 39(226.38,-29.53) 40(226.38,-9.84) 41(226.38,9.84) 42(226.38,29.53) 43(226.38,49.21) 44(226.38,68.9) 45(226.38,88.58) 46(226.38,108.27) 47(226.38,127.95) 48(226.38,147.64)
  rect 11.81x57.09 smd: 17(-147.64,-226.38) 18(-127.95,-226.38) 19(-108.27,-226.38) 20(-88.58,-226.38) 21(-68.9,-226.38) 22(-49.21,-226.38) 23(-29.53,-226.38) 24(-9.84,-226.38) 25(9.84,-226.38) 26(29.53,-226.38) 27(49.21,-226.38) 28(68.9,-226.38) 29(88.58,-226.38) 30(108.27,-226.38) 31(127.95,-226.38) 32(147.64,-226.38) 49(147.64,226.38) 50(127.95,226.38) 51(108.27,226.38) 52(88.58,226.38) 53(68.9,226.38) 54(49.21,226.38) 55(29.53,226.38) 56(9.84,226.38) 57(-9.84,226.38) 58(-29.53,226.38) 59(-49.21,226.38) 60(-68.9,226.38) 61(-88.58,226.38) 62(-108.27,226.38) 63(-127.95,226.38) 64(-147.64,226.38)
  silkscreen extent -229,176 -219,186, body extent -236,-236 236,236, height 63
RESC0402(1005)_L [mm] "Chip Resistor, Body 1.0x0.5mm, IPC High Density"
  rrect25% 0.5x0.55 smd: 1(-0.45,0) 2(0.45,0)
  silkscreen extent 0,-0.2 0,0.2, body extent -0.5,-0.25 0.5,0.25, height 0.3
RESC0603(1608)_L [mm] "Chip Resistor, Body 1.6x0.8mm, IPC High Density"
  rrect25% 0.66x0.76 smd: 1(-0.7,0) 2(0.7,0)
  silkscreen extent 0,-0.3 0,0.3, body extent -0.8,-0.4 0.8,0.4, height 0.45
RESC1005X40X25ML05T05 [mm] "Chip Resistor, 2-Leads, Body 1.05x0.55mm, IPC Low Density"
  rect 0.65x0.65 smd: 1(-0.5,0) 2(0.5,0)
  body extent -0.53,-0.28 0.53,0.28, height 0.4
RESC1005X40X25ML10T10 [mm] "Chip Resistor, 2-Leads, Body 1.1x0.6mm, IPC Low Density"
  rect 0.75x0.7 smd: 1(-0.475,0) 2(0.475,0)
  body extent -0.55,-0.27 0.55,0.28, height 0.4
RESC1608X55X25ML10T15 [mm] "Chip Resistor, 2-Leads, Body 1.70x0.90mm, IPC Low Density"
  rect 0.8x1 smd: 1(-0.75,0) 2(0.75,0)
  body extent -0.85,-0.45 0.85,0.45, height 0.55
SH-2P-SIDE [mm] "Side entry type"
  rect 0.6x1.55 smd: 1(-0.5,0) 2(0.5,0)
  rect 1.2x1.8 smd: X(-1.8,-3.875) X(1.8,-3.875)
  silkscreen extent -2,-4.5 2,-0.5
SH-04-SIDE [mm]
  rect 0.6x1.55 smd: 1(-0.5,0) 2(0.5,0) 3(1.5,0) 4(2.5,0)
  rect 1.2x1.8 smd: X(-1.8,-3.875) X(3.8,-3.875)
  silkscreen extent -2,-4.5 4,-0.5
SH-5P-SIDE [mm] "Side Entry Type"
  rect 0.6x1.55 smd: 1(-0.5,0) 2(0.5,0) 3(1.5,0) 4(2.5,0) 5(3.5,0)
  rect 1.2x1.8 smd: X(-1.8,-3.875) X(4.8,-3.875)
  silkscreen extent -2,-4.5 5,-0.5
SOT23-6 [mil]
  rect 23.62x35.43 smd: 1(-37.4,-45.28) 2(0,-45.28) 3(37.4,-45.28) 4(37.4,45.28) 5(0,45.28) 6(-37.4,45.28)
TI-DBV5_V [mm] "SOT23, 5-Leads, Body 3.05x1.75mm, Pitch 0.95mm"
  rect 1.05x0.6 smd paste-0.025 mask+0.07: 1(-1.35,0.95) 2(-1.35,0) 3(-1.35,-0.95) 4(1.35,-0.95) 5(1.35,0.95)
  silkscreen extent -1.47,-1.45 0.43,1.92, body extent -1.5,-1.53 1.5,1.53, height 1.45
TSSOP-14 [mm]
  rect 0.26x1.35 smd: 1(-1.95,-2.925) 2(-1.3,-2.925) 3(-0.65,-2.925) 4(0,-2.925) 5(0.65,-2.925) 6(1.3,-2.925) 7(1.95,-2.925) 8(1.95,2.925) 9(1.3,2.925) 10(0.65,2.925) 11(0,2.925) 12(-0.65,2.925) 13(-1.3,2.925) 14(-1.95,2.925)
  silkscreen extent -2.5,-2 2.5,2, body extent -2.55,-3.2 2.55,3.2, height 1.1
USB-C-A40-00119 [mm]
  rect 0.6x1.27 smd: 1(-3.2,7.2) 2(-2.4,7.2) 11(2.4,7.2) 12(3.2,7.2)
  rect 0.3x1.27 smd: 3(-1.75,7.2) 4(-1.25,7.2) 5(-0.75,7.2) 6(-0.25,7.2) 7(0.25,7.2) 8(0.75,7.2) 9(1.25,7.2) 10(1.75,7.2)
  oval 1x2.2 hole 0.65 slot 1.8 at 90 deg: A(-4.32,6.57) B(-4.32,2.4) C(4.32,2.4) D(4.32,6.57)
  round 0.65 hole 0.65 unplated: MH1(-2.9,6.05) MH2(2.9,6.05)
  body extent -4.47,-0.2 4.47,7.7, height 3.61
XT30PW-M [mm]
  round 2.5 hole 1.9: 1(-2.5,0) 2(2.5,0)
  round 1.6 hole 1: 3(5.5,10) 4(-5.5,10)
  silkscreen extent -6.75,2 6.75,13.05, body extent -6.65,-1 6.65,12.95, height 5

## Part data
C1 C2: library part CMP-001-00000-6, "Chip Capacitor, 6.8 nF, +/- 10%, 16 V, 0402 (1005 Metric)", Capacitor Type=Ceramic, Case/Package=0402, Max Operating Temperature=125°C, Min Operating Temperature=-55°C, Tolerance=10%, Voltage Rating=16V
C3 C11 C17 C18: library part CMP-001-00062-3, "Chip Capacitor, 22nF +/-20%, 10V, 0402, Thickness 0.6 mm", Case/Package=0402, Max Operating Temperature=85°C, Min Operating Temperature=-55°C, Tolerance=10%, Voltage Rating=10V
C4 C6 C7 C9 C12 C15: library part CMP-001-00017-6, "Chip Capacitor, 100 nF, +/- 10%, 50 V, 0603 (1608 Metric)", Capacitor Type=Ceramic, Case/Package=0603, Max Operating Temperature=125°C, Min Operating Temperature=-55°C, Tolerance=10%, Voltage Rating=50V
C5 C16 C33 C34 C35: library part CMP-001-00076-4, "Chip Capacitor, 4.7µF +/-20%, 10V, 0603, Thickness 1 mm", Case/Package=0603, Max Operating Temperature=85°C, Min Operating Temperature=-55°C, Tolerance=10%, Voltage Rating=10V
C8: library part CMP-001-00082-4, "Chip Capacitor, 47µF +/-40%, 6.3V, 0805, Thickness 1.45 mm", Case/Package=0805, Max Operating Temperature=85°C, Min Operating Temperature=-55°C, Tolerance=10%, Voltage Rating=6.3V
C10: library part CMP-001-00056-4, "Chip Capacitor, 2,2µF +/-20%, 10V, 0402, Thickness 0.6 mm", Case/Package=0402, Max Operating Temperature=85°C, Min Operating Temperature=-55°C, Tolerance=10%, Voltage Rating=10V
C13 C14: library part CMP-001-00063-3, "Chip Capacitor, 1µF +/-20%, 10V, 0402, Thickness 0.6 mm", Case/Package=0402, Max Operating Temperature=85°C, Min Operating Temperature=-55°C, Tolerance=10%, Voltage Rating=10V
C19 C20 C21 C22 C23 C24 C25 C26 C27 C28: library part CMP-001-00015-6, "Chip Capacitor, 10 uF, +/- 10%, 16 V, 0805 (2012 Metric)", Capacitor Type=Ceramic, Case/Package=0805, Max Operating Temperature=85°C, Min Operating Temperature=-55°C, Tolerance=10%, Voltage Rating=16V
C29 C30: library part CMP-001-00004-6, "Chip Capacitor, 1 uF, +/- 10%, 16 V, 0603 (1608 Metric)", Capacitor Type=Ceramic, Case/Package=0603, Max Operating Temperature=125°C, Min Operating Temperature=-55°C, Tolerance=10%, Voltage Rating=16V
C31 C36 C37 C38 C39 C40 C41 C42 C43 C44 C45 C46 C47 C48 C49 C50 C51: library part CMP-001-00067-3, "Chip Capacitor, 100nF +/-20%, 50V, 0402, Thickness 0.6 mm", Case/Package=0402, Max Operating Temperature=85°C, Min Operating Temperature=-55°C, Tolerance=10%, Voltage Rating=50V
C32: library part CMP-001-00069-3, "Chip Capacitor, 10nF +/-20%, 50V, 0402, Thickness 0.6 mm", Case/Package=0402, Max Operating Temperature=85°C, Min Operating Temperature=-55°C, Tolerance=5%, Voltage Rating=50V
D1: library part CMP-2000-05896-2, "DIODE SCHOTTKY 30V 3A SMA", Capacitance=200pF, Dc Blocking Voltage=30V, Forward Current=3A, Manufacturer=Diodes, Max Junction Temp=+150°C, Max Surge Forward Current=80A, Package=SMA, Peak Reverse Current=0.5mA, Temperature="-55°C to +150°C", Temperature Range Low=-55°C
D2: library part CMP-004-00001-2, "Small Signal Diode, 75 V, 0.15 A, -55 to 150 degC, 2-Pin SOD-323, RoHS, Tape and Reel", Capacitance=-323f, Case/Package=SOD-323, Forward Current=150mA, Forward Voltage=1V, Manufacturer=Fairchild, Max Operating Temperature=150°C, Min Operating Temperature=-55°C, Package Description="2-Pin Small Outline Diode Flat Lead, Body 1.7 x 1.25 mm", Package Quantity=3000, Peak Reverse Current=5uA
D3 D4 D5 D6 D7 D8 D9 D10 D11: library part CMP-0881-00001-1, "High Conductance Fast Switching Diode, 75 V, -55 to 150 degC, 2-Pin SOD523F, RoHS", Manufacturer="Fairchild Semiconductor", Temperature Range="-55 to 150 degC"
D12: library part CMP-12389-000001-1, "Rectifier, 1Kv, 1A, Do-214Ac Rohs Compliant: Yes"
DS1: library part CMP-007-00014-2, "LED Uni-Color Red, 65 mW, 20 mA, -40 to 85 degC, 2-Pin SMD, RoHS, Tape and Reel", Case/Package=0603, Colour=Red, Forward Current=20mA, Forward Voltage=1.8V, Manufacturer=Avago, Max Operating Temperature=85°C, Min Operating Temperature=-40°C, Package Description="2-Pin Surface Mount Device, Body 1.6 x 0.8 mm, Height 0.9 mm", Package Quantity=4000, Package Reference=HSMX-C190, Power=78mW
DS2: library part CMP-007-00025-2, "LED Uni-Color Yellow, 75 mW, 30 mA, -30 to 85 degC, 2-Pin SMD, RoHS, Tape and Reel", Case/Package=0603, Colour=Yellow, Forward Current=20mA, Forward Voltage=2V, Manufacturer=Lite-On, Max Operating Temperature=85°C, Min Operating Temperature=-55°C, Package Description="2-Pin Surface Mount Device, Body 1.6 x 0.8 mm", Package Quantity=3000, Package Reference=C190KSKT, Power=75mW
J1 J2: library part CMP-009-00061-2
L1: library part CMP-2000-06442-2, "Commercial Inductors, Low DCR Series 22uH 2.9A 135mΩ 20%", Case Code (Imperial)=2525, Case Code (Metric)=6363, Current Rating=2.9A, DC Resistance (DCR)=135mR, Inductance Tolerance=20%, Max Operating Temperature=125°C, Min Operating Temperature=-55°C, Package Quantity=2000, Saturation Current=2.5A, Self Resonant Frequency=1MHz, Test Frequency=100kHz
R1: library part CMP-009-00026-5, "Chip Resistor, 15 KOhm, +/- 1%, 0.063 W, -55 to 155 degC, 0402 (1005 Metric)", Case/Package=0402, Max Operating Temperature=155°C, Min Operating Temperature=-55°C, Power=63mW, Tolerance=1%
R2 R4 R6 R7 R8 R12 R13: library part CMP-009-00017-5, "Chip Resistor, 10 KOhm, +/- 1%, 01 W, -55 to 155 degC, 0603 (1608 Metric)", Case/Package=0603, Max Operating Temperature=155°C, Min Operating Temperature=-55°C, Power=100mW, Tolerance=1%, Voltage Rating=50V
R3: library part CMP-009-00163-3, "Chip Resistor, 200 kOhms, +/-1 %, 63 mW, -55 to 155 degC, 0402", Case/Package=0402, Max Operating Temperature=155°C, Min Operating Temperature=-55°C, Power=63mW, Tolerance=1%
R5 R9 R10: library part CMP-009-00015-5, "Chip Resistor, 10 KOhm, +/- 1%, 0.1 W, -55 to 155 degC, 0402 (1005 Metric)", Case/Package=0402, Max Operating Temperature=155°C, Min Operating Temperature=-55°C, Power=100mW, Tolerance=1%, Voltage Rating=50V
R11 R17 R18 R19 R25 R26 R27 R28 R29 R30 R31 R33 R34 R35 R36 R37 R38 R39: library part CMP-009-00005-5, "Chip Resistor, 0 Ohm, 0.1 W, -55 to 155 degC, 0402 (1005 Metric)", Case/Package=0402, Max Operating Temperature=155°C, Min Operating Temperature=-55°C, Power=100mW, Tolerance=5%, Voltage Rating=50V
R14 R15 R16 R20 R21 R22: library part CMP-009-00176-3, "Chip Resistor, 120 Ohms, +/-5 %, 0.1 W, -55 to 155 degC, 0603", Case/Package=0603, Max Operating Temperature=155°C, Min Operating Temperature=-55°C, Power=100mW, Tolerance=5%
R23 R24: library part CMP-02407-004199-1, "RES Thick Film, 100kΩ, 1%, 1W, 100ppm/°C, 2512", Case Code (Imperial)=2512, Case Code (Metric)=6432, Max Operating Temperature=155°C, Max Power Dissipation=1W, Min Operating Temperature=-55°C, Package Quantity=2000, Resistance=100kR, Temperature Coefficient=100ppm/°C, Tolerance=1%, Voltage Rating=500V
R32: library part CMP-26527-001340-1, "120Ω ±5% 0.1W 0603 Thick Film Chip Resistor AEC-Q200 compliant", Case Code (Imperial)=0603, Case Code (Metric)=1608, Max Operating Temperature=155°C, Max Power Dissipation=100mW, Min Operating Temperature=-55°C, Resistance=120R, Resistor Type="Thick Film", Temperature Coefficient=100ppm/°C, Tolerance=5%
U1: "Three phases gate driver with dual current shunt amplifiers and buck regulator"
U2: library part CMP-019-00026-3, "Single Output Low Noise LDO, 150 mA, Fixed 3.3 V Output, 1.5% Tolerance, 2.2 to 16 V Input, Low IQ, 5-Pin SOT-23 (DBV), -40 to 125 degC, Green (RoHS & no Sb/Br), Tape and Reel", Case/Package=SOT-23-5, Dropout Voltage=3mV, Manufacturer="Texas Instruments", Max Input Voltage=16V, Max Operating Temperature=125°C, Max Ouput Current=150mA, Min Input Voltage=2.2V, Min Operating Temperature=-40°C, Nominal Output Voltage=3.3V, Package Description="5-Pin Small Outline Transistor, Body 2.9 x 1.6 mm, Pitch 0.95 mm", Package Quantity=3000, Package Reference=DBV5, Package Version="4073253-4/N, 12/2014"
U4: library part CMP-0186-00138-3, "High-Speed CAN Transceiver, /  1 Mb/s, 4.5 to 5.5 V, 8-Pin SOIC (SN), Industrial Temperature, RoHS, Tube", Manufacturer=Microchip
U5: "Automotive very low capacitance ESD protection"
U6: "MCU 32-Bit, ARM Cortex M4, 1MB Flash STMicroelectronics STM32F405RGT6, 32bit ARM Cortex M4F Microcontroller, 168MHz, 1024 kB Flash, 64-Pin LQFP   Source:  Datasheet", MANUFACTURER_NAME=STMicroelectronics, Package=QFP50P1200X1200X160-64N
USB1: Package=USB-C-A40-00119
X1: library part CMP-2000-06123-1, "Ceramic Resonator, 12 MHz, +/- 0.5%, -40 to 125 degC, 3-Pin SMD, RoHS, Tape and Reel", Capacitance=33pF, Frequency Stability=±0.2%, Frequency Tolerance=±0.5%, Manufacturer=Murata, Operating Temperature=-40°C~125°C, Package / Case=3-SMD,Non-Standard, Package Description="3-Pin Surface Mount Device, Body 3.2 x 1.3 mm, Pitch 1.2 mm", Package Reference=CSTCE_G, Standard Package=1

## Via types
v1: diameter 17.72, hole 9.84, Top Layer to Bottom Layer, tented both sides, 211 vias
v2: diameter 23.62, hole 15.75, Top Layer to Bottom Layer, tented both sides, 74 vias
v3: diameter 25.59, hole 17.72, Top Layer to Bottom Layer, tented both sides, 7 vias

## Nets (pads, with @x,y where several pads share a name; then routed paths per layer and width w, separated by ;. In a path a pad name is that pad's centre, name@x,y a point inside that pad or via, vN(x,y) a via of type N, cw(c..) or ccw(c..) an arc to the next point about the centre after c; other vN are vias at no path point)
+3V3: C30.2 C40.2 C45.2 C47.2 C48.2 C50.2 C51.2 D2.2 D9.1 D10.1 D11.1 R37.1 R39.1 U1.24 U2.5 U3.11 U3.12 U6.13 U6.19 U6.32 U6.48 U6.64 | length 6643.3
  Top Layer w10: D9.1@883.12,1737.5 v1(912.5,1737.5) 951.11,1698.89 1033.23,1698.89 1050.66,1716.33 1050.66,1717.05 1056.52,1722.91 1151.87,1722.91 ; U6.64@1011.9,486.93 1012.5,486.33 C45.2@1012.5,455.22 ; C47.2@1058.32,871.85 1089.73,871.85 1090.64,870.95 U6.48@1090.64,860.95 ; D10.1@1151.87,1743.75 1151.87,1722.91 ; R39.1@1306.25,225.94 R37.1@1306.25,280.31 1321.82,295.89 1327.19,295.89 1349.02,317.72 C48.2@1350,317.72 1350,342.56 1327.76,364.8 1327.76,407.29 U6.13@1326.86,408.19 ; D11.1@1426.87,1743.75 1420.96,1743.75 1416.12,1738.91 1416.12,1715.01 1400,1698.89 1310.52,1698.89 1288.03,1721.38 1285.6,1721.38 1284.08,1722.91 1151.87,1722.91 ; 1437.5,950 1451.1,963.6 1451.1,1056.94 1462.01,1067.84 U1.24@1462.01,1108.61 ; U6.19@1464.66,526.3 1465.56,527.21 1495.88,527.21 C51.2@1512.92,544.26 ; U6.32@1464.66,782.21 1487.3,782.21 1507.52,802.44 1513.91,802.44 C50.2@1518.75,807.28
  Top Layer w16: v1(488.68,1894.93) 406.25,1812.5 406.25,1406.25 461.5,1351 675,1351 ; v3(679.65,530.64) 679.65,528.05 700,507.7 v3(700,356.25) ; v3(687.5,662.5) 687.99,662.5 743.58,718.08 743.58,750 ; v1(706.25,1350) 705.92,1350.33 685.61,1350.33 684.94,1351 675,1351 ; U2.5@843.65,865.6 839.84,861.79 839.84,805.05 837.5,802.71 C30.2@837.5,800 ; C45.2@1012.5,455.22 1038.53,455.22 1056.25,437.5 v1(1056.25,387.5) ; C47.2@1058.32,871.85 1056.47,870.01 1056.47,850.22 1031.25,825 931.25,825 906.25,800 C30.2@837.5,800 ; C48.2@1350,317.72 1381.82,317.72 1387.04,312.5 v1(1387.5,312.5) ; 1437.5,950 1437.5,949.9 1431.17,943.57 1431.17,903.9 v1(1476.87,858.2) ; C51.2@1515.92,549.19 1517.77,551.03 C51.2@1518.75,551.03 1519.46,550.33 1537.17,550.33 v1(1537.5,550) ; C50.2@1518.75,807.28 1520.59,805.44 1544.09,805.44 1549.54,800 v1(1550,800) ; 673.69,1150 673.69,1186.19 675,1187.5 ; 673.69,1150 673.69,818.15 691.85,800 727.95,800 743.58,784.38 743.58,750 ; 673.69,1150 675,1151.31 675,1187.5 ; 675,1187.5 675,1351 ; 743.58,750 746.6,753.02 821.77,753.02 837.5,768.75 C30.2@837.5,800
  Bottom Layer w10: v1(488.68,1894.93) 488.75,1895 567.5,1895 677.69,1784.81 741.75,1784.81 757.8,1768.75 812.5,1768.75 836.06,1745.19 836.06,1690.07 847.69,1678.44 884.69,1678.44 912.5,1706.25 v1(912.5,1737.5) ; U3.11@925.2,1357.91 U3.12@950.79,1357.91 950.79,1405.51 944.78,1411.52 939.52,1411.52 C40.2@938.53,1412.5
  Bottom Layer w16: D2.2@516.73,678.15 669.26,678.15 684.9,662.5 v3(687.5,662.5) 687.5,659.9 681.25,653.65 681.25,532.24 v3(679.65,530.64) ; v3(700,356.25) 781.25,437.5 1006.25,437.5 v1(1056.25,387.5) 1295.61,387.5 ; v1(706.25,1350) 706.25,1375 743.75,1412.5 C40.2@938.53,1412.5 ; v1(1387.5,312.5) 1387.5,350 1350,387.5 1295.61,387.5 ; v1(1476.87,858.2) 1477.33,858.2 1477.2,858.07 1477.2,856.66 1477.33,856.53 1477.33,550 ; 1481.25,800 v1(1550,800) ; v1(1537.5,550) 1477.33,550 ; 1295.61,387.5 1295.61,532.25 1313.36,550 1477.33,550
+5V: C8.1 C29.2 C39.2 C43.2 C44.2 D12.1 L1.2 P6.2 P9.2 R2.2 R11.1 U2.1 U2.3 U4.3 | length 3466.7
  Top Layer w12: P9.2@333.81,729.92 334.99,731.1 386.32,731.1 C44.2@387.5,732.28 ; P6.2@508.46,2046.9 511,2044.37 511,1990.03 C39.2@513.53,1987.5
  Top Layer w20: P9.2@333.81,729.92 315.11,729.92 313.3,728.11 282.49,728.11 262.5,708.12 262.5,625 343.8,543.7 437.5,543.7 ; C39.2@513.53,1987.5 513.53,1876.03 437.5,1800 437.5,1418.75 481.25,1375 718.75,1375 750,1343.75 750,1260 787.5,1222.5 L1.2@806.25,1222.5 841.68,1187.07 C8.1@841.68,1125 ; U4.3@596.85,446.8 595.97,445.93 595.97,384.51 C43.2@595.82,384.35 595.66,384.19 595.66,364.41 581.25,350 462.5,350 437.5,375 437.5,543.7 ; R11.1@718.75,917.82 771.41,917.82 ; U2.3@768.85,971.9 768.85,920.37 771.41,917.82 ; v3(842.19,696.81) 840.68,696.81 811.32,667.46 811.21,667.46 796.79,653.04 796.79,596.3 752.08,551.59 741.17,562.5 493.75,562.5 474.95,543.7 437.5,543.7 ; C29.2@844.48,1025.85 861.44,1025.85 880.87,1006.41 880.87,844.13 v3(881.25,843.75) ; R2.2@918.75,1123.28 917.89,1124.14 842.54,1124.14 C8.1@841.68,1125 ; 771.41,917.82 824.07,917.82 843.65,937.4 U2.1@843.65,971.9 841.84,973.71 841.84,1030.45 C29.2@834.79,1037.5 838.24,1040.94 838.24,1121.56 C8.1@841.68,1125
  Bottom Layer w20: v3(842.19,696.81) 842.19,804.69 v3(881.25,843.75)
